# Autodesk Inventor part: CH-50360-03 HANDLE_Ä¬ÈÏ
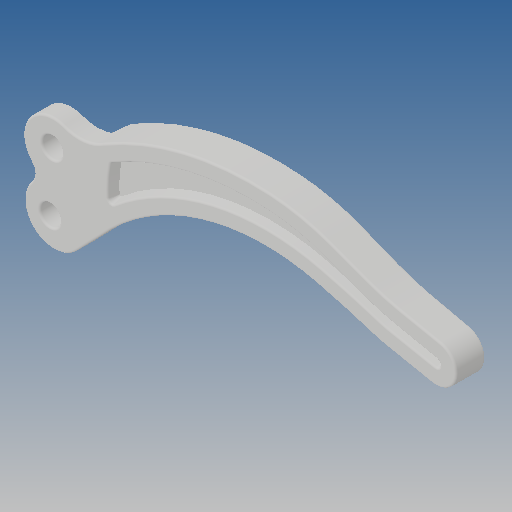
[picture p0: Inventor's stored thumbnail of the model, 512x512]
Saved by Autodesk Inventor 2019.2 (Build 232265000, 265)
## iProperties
Created: 2010-06
Part Number: CH-50360-03 HANDLE_Ä¬ÈÏ
Material: Ogólny
Document SubType Name: Modeling
Designer: CADENGINEERING4
Density: 1 g/cm^3
Appearance: Domyślna
Author: CADENGINEERING4
Revision Number: ÈÎºÎ
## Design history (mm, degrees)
feature "NONE"
node "Bryła1"
